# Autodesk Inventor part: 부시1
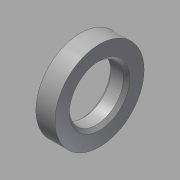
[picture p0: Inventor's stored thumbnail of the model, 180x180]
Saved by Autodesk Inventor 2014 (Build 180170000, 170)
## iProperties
Created: 2015-09
Part Number: 부시1
Material: 강철, 연강
Document SubType Name: Modeling
Designer: mduedu
Density: 7.86 g/cm^3
Description: 외주 가공
Mass: 17.8983 g
Surface Area: 15.6581 cm^2
Volume: 2.27713 cm^3
Appearance: Steel
Author: mduedu
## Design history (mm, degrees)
sketch "스케치1"
  geometry: C1 r 14 at (0, 0); C2 r 8.5 at (0, 0); 1 further point
  constraints: 2 centre point, 2 coincident
  dimensions: "d0" = 28 diameter of C1; "d2" = 17 diameter of C2
extrude "돌출1" new body sketch "스케치1" distance "d3" = 6; taper "d4" = 0 deg
chamfer "모따기1" distance "d5" = 1; stored, may be unused: second distance "d6" = 2, angle "d7" = 45 deg
node "솔리드1"
